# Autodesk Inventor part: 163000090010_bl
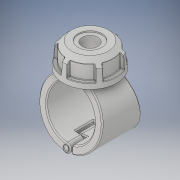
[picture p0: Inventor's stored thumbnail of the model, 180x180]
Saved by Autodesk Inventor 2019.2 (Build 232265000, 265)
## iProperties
Created: 2022-02
Part Number: 163000090010_bl
Material: Generic
Description: Plassadle Threaded 90x1''
Document SubType Name: Modeling
Designer: comp2
Density: 1 g/cm^3
Appearance: Default
Author: comp2
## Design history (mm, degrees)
derived "16300.ipt"
feature "Solid1::16300.ipt" dims "ScaleForDerivedMember" = 10
feature "Solid2::16300.ipt" dims "ScaleForDerivedMember" = 10
feature "Solid3::16300.ipt" dims "ScaleForDerivedMember" = 10
feature "Solid4::16300.ipt" dims "ScaleForDerivedMember" = 10
tag "TaggingFeature1"
body "Solid1"
body "Solid2"
body "Solid3"
body "Solid4"
other parameters: "d2" = 119 [user parameter], "d3" = 45 [user parameter], "d7" = 113.05 [user parameter], "d8" = 85 deg [user parameter], "d9" = 45 deg [user parameter], "d10" = 102 [user parameter], "d11" = 49 [user parameter], "d12" = 31.2165 [user parameter], "d13" = 42.84 [user parameter], "d14" = 45.4365 [user parameter], "d42" = 2.9 [user parameter], "d49" = 2.38 [user parameter], "d50" = 94 [user parameter], "d51" = 0 [user parameter], "d52" = 20.3 [user parameter], "d53" = 65.45 [user parameter], "d54" = 32.9 [user parameter], "d55" = 0 [user parameter], "d56" = 18.8 [user parameter], "d57" = 18.8 [user parameter], "d59" = 0 [user parameter], "d60" = 94 [user parameter], "d61" = 0 [user parameter], "d62" = 32.9 [user parameter], "d63" = 0 [user parameter], "d65" = 0 [user parameter], "d67" = 0 [user parameter], "d69" = 0 [user parameter], "d70" = 1 [user parameter], "d71" = 90.24 [user parameter], "d72" = 0 [user parameter], "d73" = 2 [user parameter], "d78" = 86.7 [user parameter], "d79" = 5.1 [user parameter], "d80" = 60 deg [user parameter], "d81" = 5.1 [user parameter], "d84" = 0 [user parameter], "d85" = 1 [user parameter], "d87" = 360 deg [user parameter], "d122" = 49 [user parameter], "d124" = 42.80128 [user parameter], "d125" = 2.22975 [user parameter], "d127" = 163 [user parameter], "d129" = 30.291 [user parameter], "d130" = 25.74735 [user parameter], "d131" = 31.85 [user parameter], "d132" = 45 deg [user parameter], "d133" = 22.295 [user parameter], "d134" = 15.1455 [user parameter], "d136" = 0 [user parameter], "d138" = 0 [user parameter], "d1" = 25 [user parameter], "B" = 119 [user parameter], "L" = 94 [user parameter], "E_" = 54 [user parameter], "E1" = 102 [user parameter], "H1" = 163 [user parameter], "H2" = 49 [user parameter], "H3" = 78 [user parameter], "H_costum" = 49 [user parameter], "Rp" = 30.291 [user parameter], "d128" = 44.595 [user parameter]
